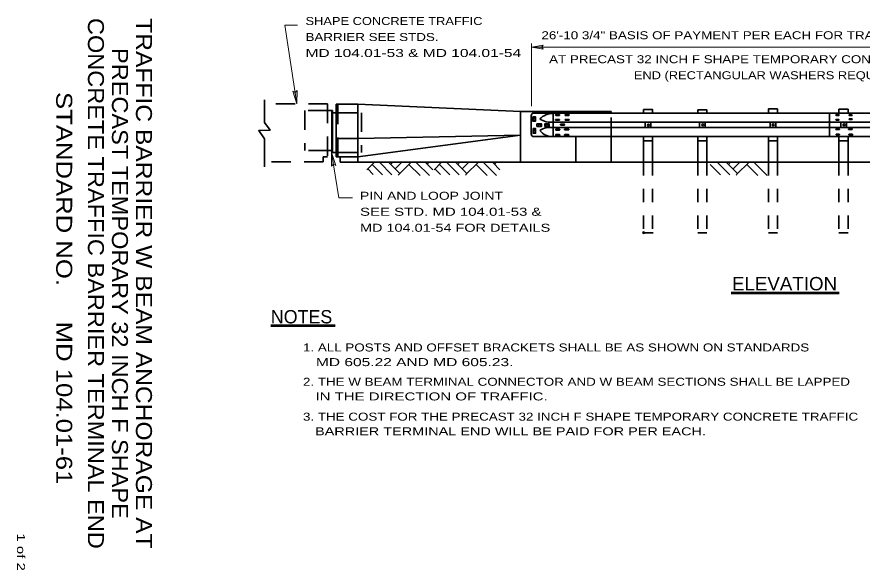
# Model space of a CAD drawing. Extents: x 49.7 to 60, y 209.2 to 216.1.
# Drawn here: x 49.75 to 56.09, y 209.18 to 213.33 of the extents above; entities that cross this region are included whole.
import ezdxf
from ezdxf.enums import TextEntityAlignment as Align

# ---------------------------------------------------------------- set-up
doc = ezdxf.new("R2010")
doc.units = 0
doc.header["$LTSCALE"] = 0.024
doc.header["$PDMODE"] = 32
doc.header["$PDSIZE"] = 0.012
doc.linetypes.add('LONG_DASHED', pattern=[7.5, 6, -1.5])
doc.linetypes.add('MEDIUM_DASHED', pattern=[4.5, 3, -1.5])
for name, color, linetype, lineweight in [('1', 7, 'Continuous', 35), ('10', 7, 'Continuous', 13), ('12', 7, 'Continuous', 53), ('13', 7, 'Continuous', 53), ('6', 7, 'Continuous', 13)]:
    doc.layers.add(name, color=color, linetype=linetype, lineweight=lineweight)

msp = doc.modelspace()

# ---------------------------------------------------------------- hatches: boundary and pattern name
at = {"layer": '10'}
for points in [[(53.69425, 213.08967), (53.60783, 213.10408), (53.69425, 213.11842), (53.68342, 213.10408)], [(51.84908, 212.7805), (51.84758, 212.67833), (51.81583, 212.77542), (51.83433, 212.76558)], [(52.14033, 212.21717), (52.10792, 212.31408), (52.10717, 212.21175), (52.12167, 212.22683)]]:
    msp.add_hatch(color=256, dxfattribs=at).paths.add_polyline_path(points)

# ---------------------------------------------------------------- linework, layer by layer
at = {"layer": '1', "linetype": 'LONG_DASHED'}
for p, q in [((52.07792, 212.67833), (51.60433, 212.67833)), ((52.07792, 212.67833), (52.07792, 212.282)), ((52.1535, 212.28283), (52.1535, 212.67625)), ((51.90758, 212.62858), (51.90758, 212.33033)), ((52.07692, 212.62858), (51.90758, 212.62858)), ((52.15275, 212.61275), (52.33142, 212.61275)), ((52.33142, 212.61275), (52.33142, 212.3145)), ((54.20317, 212.43308), (54.20317, 212.60208)), ((52.07792, 212.33033), (51.90758, 212.33033)), ((52.07792, 212.282), (52.04525, 212.282)), ((52.04525, 212.282), (52.04525, 212.24442)), ((52.15275, 212.3145), (52.33142, 212.3145)), ((52.04525, 212.24442), (51.60092, 212.24442))]:
    msp.add_line(p, q, dxfattribs=at)
at = {"layer": '1'}
for p, q in [((52.14092, 212.67625), (52.30367, 212.67625)), ((52.14092, 212.28283), (52.14092, 212.67625)), ((52.30367, 212.67625), (53.52475, 212.62192)), ((52.30367, 212.67625), (52.30367, 212.24433)), ((52.07792, 212.62883), (52.11458, 212.62883)), ((52.10867, 212.62875), (52.10867, 212.31417)), ((52.14133, 212.613), (52.10967, 212.613)), ((52.11458, 212.62875), (52.11458, 212.31417)), ((53.60417, 212.59025), (53.60417, 212.45392)), ((53.62417, 212.61033), (59.43725, 212.61033)), ((53.76975, 212.60767), (53.76975, 212.43467)), ((53.78842, 212.59883), (53.81583, 212.59883)), ((53.81583, 212.59225), (53.78842, 212.59225)), ((53.86025, 212.5995), (53.88767, 212.5995)), ((53.88767, 212.59292), (53.86025, 212.59292)), ((54.20317, 212.62192), (54.20317, 212.61033)), ((55.84167, 212.43342), (55.84167, 212.60883)), ((55.89117, 212.59808), (55.91183, 212.59808)), ((55.91183, 212.59308), (55.89117, 212.59308)), ((55.98917, 212.59658), (56.00983, 212.59658)), ((56.00983, 212.59158), (55.98917, 212.59158)), ((53.77083, 212.5425), (58.51725, 212.5425)), ((53.78842, 212.56308), (53.81583, 212.56308)), ((53.81583, 212.55642), (53.78842, 212.55642)), ((53.82642, 212.52725), (53.85383, 212.52725)), ((53.86025, 212.56308), (53.88767, 212.56308)), ((53.88767, 212.55642), (53.86025, 212.55642)), ((54.46, 212.54233), (54.46, 212.50258)), ((54.50225, 212.54075), (54.50225, 212.50383)), ((54.86775, 212.54558), (54.86775, 212.50575)), ((54.91, 212.544), (54.91, 212.507)), ((55.39567, 212.544), (55.39567, 212.50417)), ((55.43783, 212.54233), (55.43783, 212.50542)), ((55.89075, 212.5625), (55.91125, 212.5625)), ((55.91125, 212.5575), (55.89075, 212.5575)), ((55.92675, 212.544), (55.92675, 212.50417)), ((55.969, 212.54233), (55.969, 212.50542)), ((55.99017, 212.5675), (56.01075, 212.5675)), ((56.01075, 212.5625), (55.99017, 212.5625)), ((53.76975, 212.50183), (58.52367, 212.50183)), ((53.78975, 212.48942), (53.81717, 212.48942)), ((53.81717, 212.48275), (53.78975, 212.48275)), ((53.85383, 212.52058), (53.82642, 212.52058)), ((53.85683, 212.49008), (53.88425, 212.49008)), ((53.88425, 212.48342), (53.85683, 212.48342)), ((55.89108, 212.49183), (55.91408, 212.49183)), ((55.91408, 212.48617), (55.89108, 212.48617)), ((55.9855, 212.49308), (56.011, 212.49308)), ((56.011, 212.48692), (55.9855, 212.48692)), ((52.14092, 212.4185), (52.30367, 212.4185)), ((52.30367, 212.28283), (53.52475, 212.44567)), ((52.30367, 212.4185), (53.52475, 212.44567)), ((53.62417, 212.43392), (58.52367, 212.43392)), ((53.78975, 212.4495), (53.81717, 212.4495)), ((53.81717, 212.44283), (53.78975, 212.44283)), ((53.85683, 212.4495), (53.88425, 212.4495)), ((53.88425, 212.44283), (53.85683, 212.44283)), ((53.93858, 212.24208), (53.93858, 212.43308)), ((54.20317, 212.24208), (54.20317, 212.43308)), ((54.44725, 212.24208), (54.44725, 212.43208)), ((54.44725, 212.40117), (54.51517, 212.40117)), ((54.51517, 212.24208), (54.51517, 212.43208)), ((54.85425, 212.24208), (54.85425, 212.43208)), ((54.85425, 212.40117), (54.92217, 212.40117)), ((54.92217, 212.24208), (54.92217, 212.43208)), ((55.38342, 212.24208), (55.38342, 212.43208)), ((55.38342, 212.40117), (55.45125, 212.40117)), ((55.45125, 212.24208), (55.45125, 212.43208)), ((55.89208, 212.45192), (55.915, 212.45192)), ((55.915, 212.44642), (55.89208, 212.44642)), ((55.91258, 212.24208), (55.91258, 212.43208)), ((55.91258, 212.40117), (55.98042, 212.40117)), ((55.98042, 212.24208), (55.98042, 212.43208)), ((55.98808, 212.45125), (56.0135, 212.45125)), ((56.0135, 212.44508), (55.98808, 212.44508)), ((52.07892, 212.33), (52.11458, 212.33)), ((52.14133, 212.31417), (52.10867, 212.31417)), ((52.14092, 212.28283), (52.30367, 212.28283)), ((52.17283, 212.24208), (52.17283, 212.28283)), ((52.17283, 212.24208), (54.20317, 212.24208)), ((52.17283, 212.24208), (52.575, 212.24208)), ((54.20317, 212.24208), (59.437, 212.24208))]:
    msp.add_line(p, q, dxfattribs=at)
at = {"layer": '1', "linetype": 'MEDIUM_DASHED'}
for p, q in [((54.44725, 212.24208), (54.44725, 211.713)), ((54.51517, 212.24208), (54.51517, 211.713)), ((54.85425, 212.24208), (54.85425, 211.713)), ((54.92217, 212.24208), (54.92217, 211.713)), ((55.38342, 212.24208), (55.38342, 211.713)), ((55.45125, 212.24208), (55.45125, 211.713)), ((55.91258, 212.24208), (55.91258, 211.713)), ((55.98042, 212.24208), (55.98042, 211.713)), ((54.44725, 211.713), (54.51958, 211.713)), ((54.85425, 211.713), (54.92217, 211.713)), ((55.38342, 211.713), (55.45125, 211.713)), ((55.91258, 211.713), (55.98042, 211.713))]:
    msp.add_line(p, q, dxfattribs=at)
at = {"layer": '1'}
for points in [[(54.20317, 212.62192), (53.95892, 212.62192), (53.52475, 212.62192), (53.52475, 212.24208)], [(54.44725, 212.60867), (54.44725, 212.63583), (54.51517, 212.63583), (54.51517, 212.60867)], [(54.85425, 212.60683), (54.85425, 212.63408), (54.92217, 212.63408), (54.92217, 212.60683)], [(55.38342, 212.61458), (55.38342, 212.64167), (55.45125, 212.64167), (55.45125, 212.61458)], [(55.91258, 212.61175), (55.91258, 212.63883), (55.98042, 212.63883), (55.98042, 212.61175)]]:
    msp.add_lwpolyline(points, dxfattribs=at)
for points in [[(53.61692, 212.58292), (53.63625, 212.58292), (53.63625, 212.5485), (53.61692, 212.5485)], [(53.64733, 212.50983), (53.64733, 212.52917), (53.68183, 212.52917), (53.68183, 212.50983)], [(53.70542, 212.50983), (53.70542, 212.52917), (53.73983, 212.52917), (53.73983, 212.50983)], [(53.61833, 212.49342), (53.63775, 212.49342), (53.63775, 212.459), (53.61833, 212.459)]]:
    msp.add_lwpolyline(points, close=True, dxfattribs=at)
for centre, radius in [((53.62692, 212.56496), 0.00864), ((53.66496, 212.5202), 0.00864), ((53.72369, 212.5202), 0.00864), ((54.48352, 212.51964), 0.00749), ((54.89123, 212.52288), 0.00749), ((55.41914, 212.52126), 0.00749), ((55.95029, 212.52126), 0.00749), ((53.62764, 212.47543), 0.00864)]:
    msp.add_circle(centre, radius, dxfattribs=at)
for centre, radius, start, end in [((53.62416, 212.59025), 0.02, 90, 180), ((53.77275, 212.45446), 0.15323, 91.14059, 133.10612), ((53.79009, 212.59546), 0.00377, 117.91346, 242.08653), ((53.81399, 212.59546), 0.00377, 297.91346, 62.08653), ((53.86194, 212.59614), 0.00377, 117.91346, 242.08653), ((53.88584, 212.59614), 0.00377, 297.91346, 62.08653), ((55.89246, 212.59552), 0.00283, 117.91346, 242.08653), ((55.91042, 212.59552), 0.00283, 297.91346, 62.08653), ((55.99045, 212.59402), 0.00283, 117.91346, 242.08653), ((56.0084, 212.59402), 0.00283, 297.91346, 62.08653), ((53.75328, 212.70003), 0.15857, 237.48367, 276.35124), ((53.79009, 212.55965), 0.00377, 117.91346, 242.08653), ((53.81399, 212.55965), 0.00377, 297.91346, 62.08653), ((53.82809, 212.52385), 0.00377, 117.91346, 242.08653), ((53.85199, 212.52385), 0.00377, 297.91346, 62.08653), ((53.86194, 212.55965), 0.00377, 117.91346, 242.08653), ((53.88584, 212.55965), 0.00377, 297.91346, 62.08653), ((55.89196, 212.55998), 0.00283, 117.91346, 242.08653), ((55.90992, 212.55998), 0.00283, 297.91346, 62.08653), ((55.99145, 212.56498), 0.00283, 117.91346, 242.08653), ((56.00941, 212.56498), 0.00283, 297.91346, 62.08653), ((53.75114, 212.34787), 0.155, 83.12348, 121.80821), ((53.75851, 212.54383), 0.10982, 215.79968, 275.84754), ((53.79145, 212.486), 0.00377, 117.91346, 242.08653), ((53.81535, 212.486), 0.00377, 297.91346, 62.08653), ((53.8585, 212.48668), 0.00377, 117.91346, 242.08653), ((53.8824, 212.48668), 0.00377, 297.91346, 62.08653), ((55.89261, 212.48893), 0.00315, 117.91346, 242.08653), ((55.91256, 212.48893), 0.00315, 297.91346, 62.08653), ((55.98713, 212.48998), 0.0035, 117.91346, 242.08653), ((56.00929, 212.48998), 0.0035, 297.91346, 62.08653), ((53.62416, 212.45391), 0.02, 180, 269.99999), ((53.79145, 212.44607), 0.00377, 117.91346, 242.08653), ((53.81535, 212.44607), 0.00377, 297.91346, 62.08653), ((53.8585, 212.44607), 0.00377, 117.91346, 242.08653), ((53.8824, 212.44607), 0.00377, 297.91346, 62.08653), ((55.89345, 212.44909), 0.00315, 117.91346, 242.08653), ((55.9134, 212.44909), 0.00315, 297.91346, 62.08653), ((55.98969, 212.44809), 0.0035, 117.91346, 242.08653), ((56.01185, 212.44809), 0.0035, 297.91346, 62.08653)]:
    msp.add_arc(centre, radius, start, end, dxfattribs=at)
msp.add_point((54.44725, 211.713), dxfattribs=at)
at = {"layer": '10'}
for p, q in [((51.75725, 213.27075), (51.85208, 213.27075)), ((51.75725, 213.27075), (51.84758, 212.67833)), ((53.60783, 212.66233), (53.60783, 213.13283)), ((53.69425, 213.11842), (53.60783, 213.10408)), ((53.60783, 213.10408), (58.06392, 213.10408)), ((53.69425, 213.08967), (53.60783, 213.10408)), ((53.69425, 213.11842), (53.68342, 213.10408)), ((53.69425, 213.08967), (53.68342, 213.10408)), ((51.84908, 212.7805), (51.83433, 212.76558)), ((51.84908, 212.7805), (51.84758, 212.67833)), ((51.81583, 212.77542), (51.84758, 212.67833)), ((51.81583, 212.77542), (51.83433, 212.76558)), ((52.10717, 212.21175), (52.10792, 212.31408)), ((52.10792, 212.31408), (52.16183, 211.97458)), ((52.14033, 212.21717), (52.10792, 212.31408)), ((52.10717, 212.21175), (52.12167, 212.22683)), ((52.14033, 212.21717), (52.12167, 212.22683)), ((52.26375, 211.97458), (52.16183, 211.97458))]:
    msp.add_line(p, q, dxfattribs=at)
at = {"layer": '10', "lineweight": 35}
for p, q in [((51.60317, 212.709), (51.60317, 212.54058)), ((51.60317, 212.41717), (51.60317, 212.20775))]:
    msp.add_line(p, q, dxfattribs=at)
at = {"layer": '10'}
for points in [[(53.69425, 213.08967), (53.60783, 213.10408), (53.69425, 213.11842), (53.68342, 213.10408)], [(51.84908, 212.7805), (51.84758, 212.67833), (51.81583, 212.77542), (51.83433, 212.76558)], [(52.14033, 212.21717), (52.10792, 212.31408), (52.10717, 212.21175), (52.12167, 212.22683)]]:
    msp.add_lwpolyline(points, close=True, dxfattribs=at)
at = {"layer": '10', "lineweight": 35}
msp.add_lwpolyline([(51.60317, 212.54058), (51.64683, 212.481), (51.56158, 212.47883), (51.60317, 212.41717)], dxfattribs=at)
at = {"layer": '12'}
msp.add_line((55.10475, 211.26208), (55.9145, 211.26208), dxfattribs=at)
at = {"layer": '13'}
msp.add_line((51.65192, 211.01575), (52.13458, 211.01575), dxfattribs=at)
at = {"layer": '6'}
for p, q in [((52.372, 212.18508), (52.42817, 212.24092)), ((52.49033, 212.14792), (52.4125, 212.22558)), ((52.5605, 212.14642), (52.46617, 212.24075)), ((52.61867, 212.15692), (52.53583, 212.23958)), ((52.55, 212.22558), (52.56383, 212.23942)), ((52.58433, 212.19108), (52.63183, 212.23842)), ((52.61867, 212.15692), (52.69967, 212.23758)), ((52.77083, 212.14208), (52.6875, 212.22558)), ((52.84083, 212.14075), (52.74467, 212.23692)), ((52.86633, 212.18408), (52.8145, 212.23608)), ((52.825, 212.22558), (52.83517, 212.23575)), ((52.8755, 212.18508), (52.93167, 212.24092)), ((52.99383, 212.14792), (52.916, 212.22558)), ((53.064, 212.14642), (52.96967, 212.24075)), ((53.12217, 212.15692), (53.03933, 212.23958)), ((53.0535, 212.22558), (53.06733, 212.23942)), ((53.08783, 212.19108), (53.13533, 212.23842)), ((53.12217, 212.15692), (53.20317, 212.23758)), ((53.27433, 212.14208), (53.191, 212.22558)), ((53.34433, 212.14075), (53.24817, 212.23692)), ((53.36983, 212.18408), (53.318, 212.23608)), ((53.3285, 212.22558), (53.33867, 212.23575)), ((55.02417, 212.14792), (54.94633, 212.22558)), ((55.09433, 212.14642), (55, 212.24075)), ((55.1525, 212.15692), (55.06967, 212.23958)), ((55.08383, 212.22558), (55.09767, 212.23942)), ((55.11817, 212.19108), (55.16567, 212.23842)), ((55.1525, 212.15692), (55.2335, 212.23758)), ((55.30467, 212.14208), (55.22133, 212.22558)), ((55.37467, 212.14075), (55.2785, 212.23692)), ((52.42017, 212.14925), (52.37833, 212.19108)), ((52.60733, 212.14542), (52.61867, 212.15692)), ((52.92367, 212.14925), (52.88183, 212.19108)), ((53.11083, 212.14542), (53.12217, 212.15692)), ((55.14117, 212.14542), (55.1525, 212.15692))]:
    msp.add_line(p, q, dxfattribs=at)

# ---------------------------------------------------------------- texts
at = {"layer": '12'}
for s, width, p in [('SHAPE CONCRETE TRAFFIC', 1.2, (51.912, 213.27067)), ('BARRIER SEE STDS.', 1.25, (51.912, 213.15067)), ('MD 104.01-53 & MD 104.01-54', 1.45, (51.912, 213.03067)), ('PIN AND LOOP JOINT', 1.3, (52.3205, 211.95992)), ('SEE STD. MD 104.01-53 &', 1.4, (52.3205, 211.83992)), ('MD 104.01-54 FOR DETAILS', 1.35, (52.3205, 211.71992))]:
    msp.add_text(s, height=0.06001, dxfattribs=dict(at, width=width)).set_placement(p)
for s, height, width, p in [(' 26\'-10 3/4" BASIS OF PAYMENT PER EACH FOR TRAFFIC BARRIER W BEAM ANCHORAGE', 0.06001, 1.25, (55.8155, 213.164)), ('AT PRECAST 32 INCH F SHAPE TEMPORARY CONCRETE TRAFFIC BARRIER TERMINAL', 0.06001, 1.25, (55.84554, 212.984)), ('END (RECTANGULAR WASHERS REQUIRED ON THIS SECTION)', 0.06001, 1.2, (55.84554, 212.86392)), ('ELEVATION', 0.1, 1.05, (55.50417, 211.28067))]:
    msp.add_text(s, height=height, dxfattribs=dict(at, width=width)).set_placement(p, align=Align.CENTER)
at = {"layer": '13'}
for s, width, p in [('CONCRETE TRAFFIC BARRIER TERMINAL END', 1.1, (50.28025, 211.33267)), ('TRAFFIC BARRIER W BEAM ANCHORAGE AT', 1.15, (50.64033, 211.33258)), ('PRECAST TEMPORARY 32 INCH F SHAPE', 1.1, (50.46033, 211.3325)), ('STANDARD NO.     MD 104.01-61', 1.2, (50.04217, 211.29671))]:
    msp.add_text(s, height=0.12, rotation=270, dxfattribs=dict(at, width=width)).set_placement(p, align=Align.CENTER)
msp.add_text('NOTES', height=0.1, dxfattribs=at).set_placement((51.65183, 211.03275))
for s, width, p in [('1. ALL POSTS AND OFFSET BRACKETS SHALL BE AS SHOWN ON STANDARDS', 1.25, (51.89308, 210.82208)), ('   MD 605.22 AND MD 605.23.', 1.45, (51.89308, 210.71208)), ('2. THE W BEAM TERMINAL CONNECTOR AND W BEAM SECTIONS SHALL BE LAPPED', 1.25, (51.89308, 210.56475)), ('   IN THE DIRECTION OF TRAFFIC.', 1.4, (51.89308, 210.45475)), ('3. THE COST FOR THE PRECAST 32 INCH F SHAPE TEMPORARY CONCRETE TRAFFIC', 1.25, (51.89308, 210.303)), ('   BARRIER TERMINAL END WILL BE PAID FOR PER EACH.', 1.35, (51.89308, 210.193))]:
    msp.add_text(s, height=0.06001, dxfattribs=dict(at, width=width)).set_placement(p)
at = {"layer": '13', "width": 1.4}
msp.add_text('1 of 2', height=0.06, rotation=270, dxfattribs=at).set_placement((49.74842, 209.4575))

doc.saveas('drawing.dxf')
